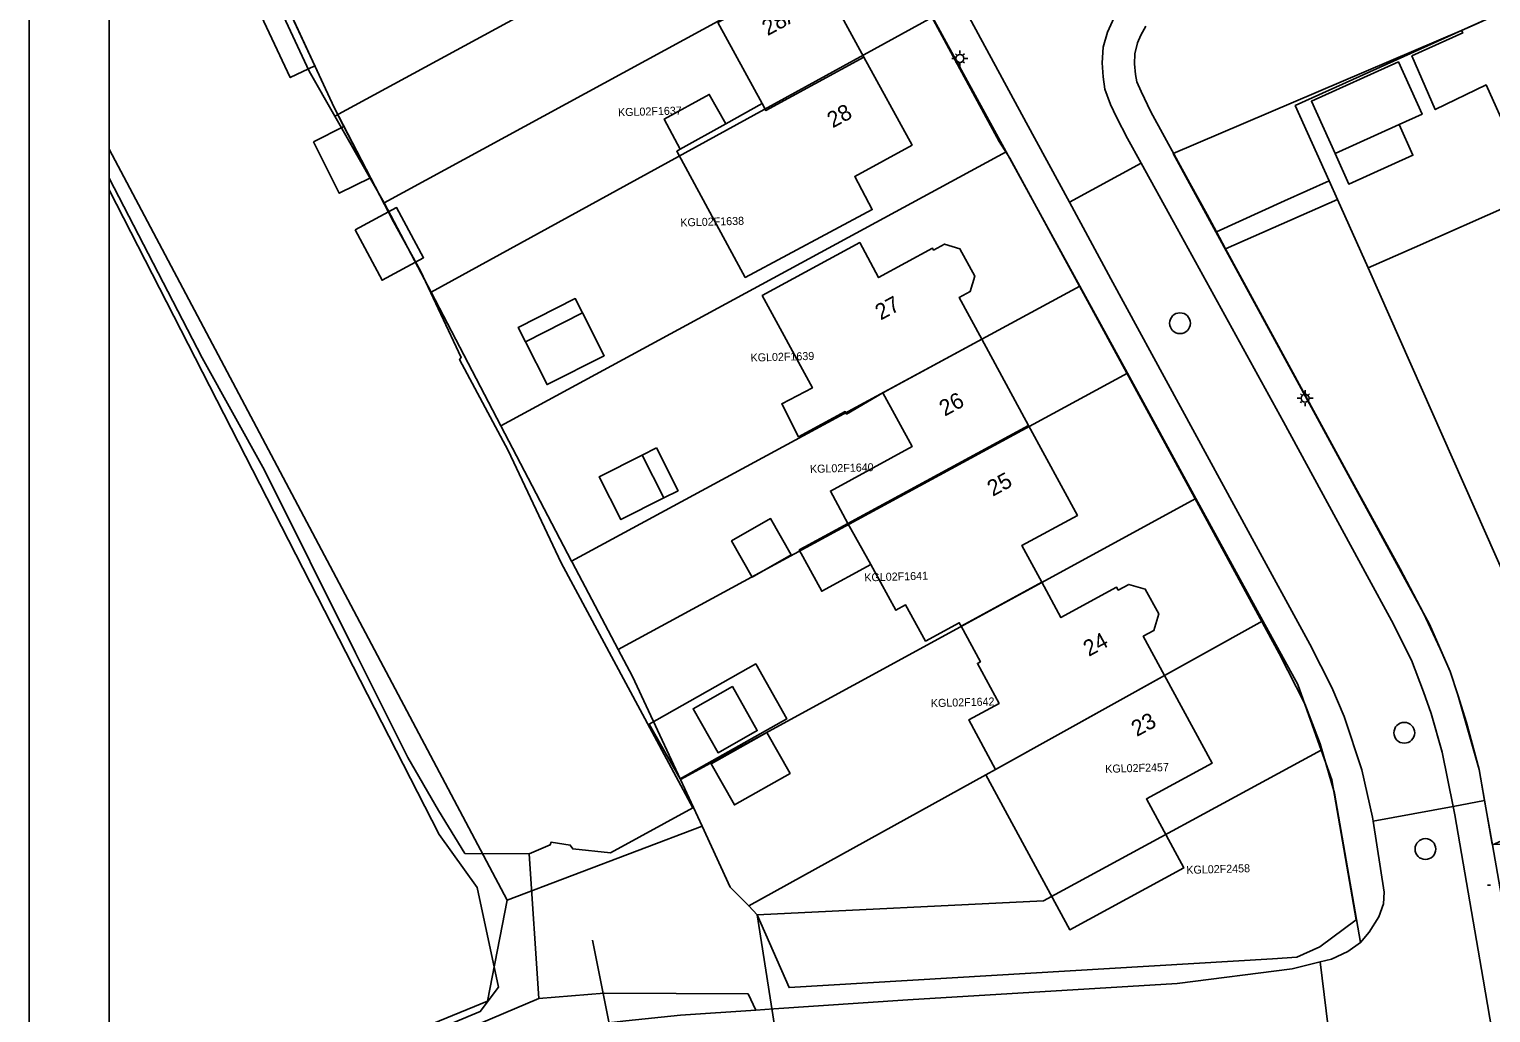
# Model space of a CAD drawing. Extents: x 124901 to 125496, y 515369 to 515789.
# Drawn here: x 124901.4 to 124992.7, y 515689 to 515750.4 of the extents above; entities that cross this region are included whole.
import ezdxf

# ---------------------------------------------------------------- set-up
doc = ezdxf.new("R2010")
doc.units = 0
for name, color, linetype in [('Alg Kaders', 7, 'Continuous'), ('Berm', 7, 'Continuous'), ('Gebouw', 7, 'Continuous'), ('Inrit', 7, 'Continuous'), ('Kunstwerkdeel', 7, 'Continuous'), ('Lichtmast', 7, 'Continuous'), ('Luifel', 7, 'Continuous'), ('Onbegroeid terrein', 7, 'Continuous'), ('Perceelnummers', 7, 'Continuous'), ('Perceelsgrenzen', 7, 'Continuous'), ('Putten', 7, 'Continuous'), ('Scheiding', 7, 'Continuous'), ('Teksten', 7, 'Continuous'), ('Vegetatie', 7, 'Continuous'), ('Voetpad', 7, 'Continuous'), ('Water', 7, 'Continuous'), ('Wegen drempel verkeerseiland', 7, 'Continuous'), ('Wegen lokale weg', 7, 'Continuous')]:
    doc.layers.add(name, color=color, linetype=linetype)

msp = doc.modelspace()

# ---------------------------------------------------------------- linework, layer by layer
at = {"layer": 'Alg Kaders'}
for points in [[(125495.925, 515789.043), (124901.425, 515789.043), (124901.425, 515368.543), (125495.925, 515368.543)], [(125490.925, 515784.043), (124906.425, 515784.043), (124906.425, 515373.543), (125490.925, 515373.543)]]:
    msp.add_lwpolyline(points, close=True, dxfattribs=at)
at = {"layer": 'Berm'}
msp.add_lwpolyline([(124906.425, 515676.84), (124909.922, 515678.313), (124922.189, 515683.579), (124929.513, 515686.462), (124932.716, 515687.441), (124934.546, 515687.912), (124936.358, 515688.167), (124938.691, 515688.452), (124942.107, 515688.795), (124946.804, 515689.111), (124946.326, 515690.139), (124937.343, 515690.17), (124933.259, 515689.839), (124919.326, 515683.927), (124906.425, 515678.456)], dxfattribs=at)
at = {"layer": 'Gebouw'}
for points in [[(124992.435, 515746.875), (124993.918, 515743.588), (125010.345, 515750.999), (125010.741, 515751.178), (125007.723, 515757.866), (124991.566, 515750.577), (124990.9, 515750.276), (124990.969, 515750.123), (124987.796, 515748.689), (124989.253, 515745.345)], [(124947.447, 515745.277), (124953.563, 515748.622), (124950.554, 515754.123), (124944.438, 515750.778), (124947.203, 515745.723)], [(124942.096, 515742.859), (124941.873, 515742.734), (124946.148, 515734.859), (124954.086, 515739.095), (124952.991, 515741.163), (124956.571, 515743.121), (124953.563, 515748.622), (124947.447, 515745.277), (124947.203, 515745.723), (124944.936, 515744.452)], [(124986.958, 515748.311), (124981.521, 515745.858), (124982.994, 515742.593), (124987, 515744.4), (124988.431, 515745.046)], [(124942.096, 515742.859), (124944.936, 515744.452), (124943.909, 515746.286), (124941.089, 515744.748)], [(124959.505, 515733.599), (124960.208, 515733.981), (124960.492, 515734.939), (124959.562, 515736.653), (124958.604, 515736.938), (124957.918, 515736.566), (124957.856, 515736.68), (124954.486, 515734.851), (124953.303, 515737.031), (124947.219, 515733.73), (124950.344, 515727.971), (124948.436, 515726.972), (124949.486, 515724.917), (124952.401, 515726.485), (124952.486, 515726.329), (124954.75, 515727.657), (124960.921, 515730.996)], [(124933.774, 515728.166), (124937.344, 515729.971), (124935.99, 515732.648), (124932.42, 515730.843)], [(124956.572, 515724.3), (124951.475, 515721.52), (124952.571, 515719.507), (124963.847, 515725.622), (124960.921, 515730.996), (124954.75, 515727.657)], [(124955.563, 515714.079), (124956.172, 515714.413), (124957.421, 515712.156), (124959.523, 515713.304), (124959.645, 515713.08), (124964.682, 515715.825), (124963.434, 515718.125), (124966.902, 515720.006), (124963.847, 515725.622), (124952.571, 515719.507), (124953.99, 515716.934), (124954.112, 515716.712)], [(124937.034, 515722.416), (124938.388, 515719.739), (124941.065, 515721.093), (124939.711, 515723.77)], [(124946.582, 515716.153), (124949.023, 515717.539), (124947.739, 515719.8), (124945.298, 515718.414)], [(124960.111, 515707.23), (124961.794, 515704.129), (124972.341, 515710.006), (124971.011, 515712.458), (124971.67, 515712.815), (124971.978, 515713.851), (124971.143, 515715.389), (124970.108, 515715.696), (124969.448, 515715.338), (124969.353, 515715.514), (124965.875, 515713.627), (124964.682, 515715.825), (124959.645, 515713.08), (124960.845, 515710.866), (124960.653, 515710.762), (124962.01, 515708.261)], [(124966.425, 515694.132), (124973.543, 515697.994), (124971.209, 515702.296), (124975.315, 515704.525), (124972.341, 515710.006), (124961.794, 515704.129), (124961.182, 515703.797)], [(124945.35, 515709.316), (124942.899, 515707.932), (124944.453, 515705.181), (124946.904, 515706.564)], [(124944.029, 515704.492), (124945.474, 515701.93), (124948.95, 515703.891), (124947.504, 515706.453)]]:
    msp.add_lwpolyline(points, close=True, dxfattribs=at)
at = {"layer": 'Inrit'}
msp.add_lwpolyline([(124975.594, 515737.699), (124976.149, 515736.646), (124983.139, 515739.734), (124982.62, 515740.889), (124979.845, 515739.652)], close=True, dxfattribs=at)
at = {"layer": 'Kunstwerkdeel'}
for points in [[(124915.267, 515752.592), (124917.728, 515747.339), (124919.268, 515748.061), (124916.832, 515753.326)], [(124919.183, 515743.334), (124920.793, 515740.112), (124922.747, 515741.089), (124921.084, 515744.284)], [(124921.775, 515737.827), (124923.468, 515734.688), (124926.062, 515736.087), (124924.37, 515739.225)]]:
    msp.add_lwpolyline(points, close=True, dxfattribs=at)
msp.add_lwpolyline([(124939.341, 515679.835), (124936.612, 515693.481)], dxfattribs=at)
at = {"layer": 'Lichtmast'}
for p, q in [((124959.349, 515748.75), (124959.279, 515748.821)), ((124959.561, 515748.838), (124959.561, 515749.038)), ((124959.773, 515748.75), (124959.844, 515748.822)), ((124959.261, 515748.539), (124959.061, 515748.538)), ((124959.349, 515748.326), (124959.277, 515748.255)), ((124959.561, 515748.238), (124959.561, 515748.038)), ((124959.773, 515748.326), (124959.843, 515748.255)), ((124959.861, 515748.538), (124960.061, 515748.538)), ((124981.122, 515727.618), (124981.122, 515727.818)), ((124980.822, 515727.319), (124980.622, 515727.318)), ((124980.91, 515727.106), (124980.838, 515727.035)), ((124980.91, 515727.53), (124980.84, 515727.601)), ((124981.122, 515727.018), (124981.122, 515726.818)), ((124981.334, 515727.53), (124981.405, 515727.602)), ((124981.334, 515727.106), (124981.404, 515727.035)), ((124981.422, 515727.318), (124981.622, 515727.318)), ((124992.715, 515696.92), (124992.515, 515696.919))]:
    msp.add_line(p, q, dxfattribs=at)
for centre in [(124959.561, 515748.538), (124981.122, 515727.318)]:
    msp.add_circle(centre, 0.25, dxfattribs=at)
at = {"layer": 'Luifel'}
for points in [[(124982.994, 515742.593), (124983.856, 515740.684), (124987.861, 515742.491), (124987, 515744.4)], [(124935.99, 515732.648), (124935.538, 515733.541), (124931.969, 515731.735), (124932.42, 515730.843)], [(124940.604, 515724.221), (124939.711, 515723.77), (124941.065, 515721.093), (124941.958, 515721.544)], [(124949.868, 515718.037), (124949.523, 515717.849), (124950.927, 515715.268), (124953.99, 515716.934), (124952.571, 515719.507)], [(124940.158, 515706.976), (124942.096, 515703.545), (124948.747, 515707.298), (124946.81, 515710.731)], [(124944.453, 515705.181), (124942.899, 515707.932), (124945.35, 515709.316), (124946.904, 515706.564)]]:
    msp.add_lwpolyline(points, close=True, dxfattribs=at)
at = {"layer": 'Onbegroeid terrein'}
for points in [[(124916.618, 515753.787), (124920.468, 515745.467), (124924.184, 515738.328), (124925.873, 515735.275), (124928.397, 515729.851), (124928.311, 515729.738), (124931.351, 515724.06), (124934.651, 515717.039), (124942.88, 515701.747), (124937.733, 515698.928), (124935.373, 515699.178), (124935.223, 515699.423), (124934.039, 515699.601), (124933.973, 515699.441), (124932.658, 515698.862), (124933.259, 515689.839), (124937.343, 515690.17), (124946.326, 515690.139), (124946.804, 515689.111), (124947.93, 515689.187), (124956.314, 515689.751), (124973.14, 515690.777), (124980.32, 515691.695), (124982.059, 515692.12), (124982.77, 515692.294), (124983.796, 515692.765), (124984.587, 515693.335), (124984.256, 515695.245), (124982.971, 515702.653), (124982.067, 515705.75), (124981.112, 515708.231), (124979.504, 515711.383), (124972.903, 515723.54), (124962.689, 515742.297), (124962.015, 515743.343), (124941.47, 515781.335)], [(124950.554, 515754.123), (124953.563, 515748.622), (124956.571, 515743.121), (124952.991, 515741.163), (124954.086, 515739.095), (124946.148, 515734.859), (124941.873, 515742.734), (124942.096, 515742.859), (124941.089, 515744.748), (124943.909, 515746.286), (124944.936, 515744.452), (124947.203, 515745.723), (124944.438, 515750.778)], [(124993.918, 515743.588), (124992.435, 515746.875), (124989.253, 515745.345), (124987.796, 515748.689), (124990.969, 515750.123), (124990.9, 515750.276), (124980.509, 515745.589), (124982.62, 515740.889), (124983.139, 515739.734), (124985.058, 515735.461), (124987.951, 515736.739), (125000, 515742.06)]]:
    msp.add_lwpolyline(points, dxfattribs=at)
for points in [[(125021.18, 515738.216), (125016.204, 515749.216), (125014.573, 515748.496), (125000, 515742.06), (124987.951, 515736.739), (124985.058, 515735.461), (124999.673, 515702.472), (125000, 515702.617), (125030.815, 515716.274), (125023.591, 515732.888)], [(124981.521, 515745.858), (124986.958, 515748.311), (124988.431, 515745.046), (124987, 515744.4), (124982.994, 515742.593)], [(124961.794, 515704.129), (124960.111, 515707.23), (124962.01, 515708.261), (124960.653, 515710.762), (124960.845, 515710.866), (124959.645, 515713.08), (124959.523, 515713.304), (124957.421, 515712.156), (124956.172, 515714.413), (124955.563, 515714.079), (124954.112, 515716.712), (124953.99, 515716.934), (124952.571, 515719.507), (124951.475, 515721.52), (124956.572, 515724.3), (124954.75, 515727.657), (124952.486, 515726.329), (124952.401, 515726.485), (124949.486, 515724.917), (124948.436, 515726.972), (124950.344, 515727.971), (124947.219, 515733.73), (124953.303, 515737.031), (124954.486, 515734.851), (124957.856, 515736.68), (124957.918, 515736.566), (124958.604, 515736.938), (124959.562, 515736.653), (124960.492, 515734.939), (124960.208, 515733.981), (124959.505, 515733.599), (124960.921, 515730.996), (124963.847, 515725.622), (124966.902, 515720.006), (124963.434, 515718.125), (124964.682, 515715.825), (124965.875, 515713.627), (124969.353, 515715.514), (124969.448, 515715.338), (124970.108, 515715.696), (124971.143, 515715.389), (124971.978, 515713.851), (124971.67, 515712.815), (124971.011, 515712.458), (124972.341, 515710.006), (124975.315, 515704.525), (124971.209, 515702.296), (124973.543, 515697.994), (124966.425, 515694.132), (124961.182, 515703.797)], [(124937.344, 515729.971), (124933.774, 515728.166), (124932.42, 515730.843), (124935.99, 515732.648)], [(124938.388, 515719.739), (124937.034, 515722.416), (124939.711, 515723.77), (124941.065, 515721.093)], [(124949.023, 515717.539), (124946.582, 515716.153), (124945.298, 515718.414), (124947.739, 515719.8)], [(124942.899, 515707.932), (124945.35, 515709.316), (124946.904, 515706.564), (124944.453, 515705.181)], [(124944.029, 515704.492), (124947.504, 515706.453), (124948.95, 515703.891), (124945.474, 515701.93)]]:
    msp.add_lwpolyline(points, close=True, dxfattribs=at)
at = {"layer": 'Perceelsgrenzen'}
for points in [[(124939.831, 515784.043), (124942.181, 515779.749), (124947.7, 515769.665), (124951.905, 515761.983), (124954.881, 515756.546), (124957.852, 515751.118), (124962.459, 515742.701), (124967.05, 515734.312), (124970.025, 515728.876), (124974.299, 515721.067), (124978.481, 515713.427), (124980.664, 515709.438), (124982.132, 515705.346), (124982.796, 515703.495), (124984.315, 515694.743), (124982.043, 515693.067), (124980.61, 515692.413), (124979.086, 515692.308), (124948.888, 515690.522), (124946.892, 515695.063), (124949.333, 515679.527)], [(124906.425, 515773.675), (124907.898, 515770.764), (124911.623, 515763.401), (124916.573, 515752.754), (124918.909, 515747.729), (124920.514, 515744.921), (124923.602, 515739.522), (124926.526, 515733.933), (124930.887, 515725.594), (124935.308, 515717.138), (124935.342, 515717.073), (124938.219, 515711.628), (124939.11, 515709.943), (124942.106, 515703.52), (124943.454, 515700.593), (124931.273, 515695.979), (124906.425, 515742.864)], [(124906.425, 515742.864), (124931.273, 515695.979), (124930.052, 515689.675), (124906.425, 515679.992)], [(124906.425, 515679.992), (124930.052, 515689.675), (124931.273, 515695.979), (124943.454, 515700.593), (124945.202, 515696.797), (124946.369, 515695.624), (124946.892, 515695.063), (124949.333, 515679.527), (124950.559, 515671.725), (124944.847, 515671.033), (124938.462, 515670.08), (124938.039, 515676.742), (124932.267, 515677.429), (124931.302, 515679.813), (124927.728, 515678.841), (124906.425, 515670.235)]]:
    msp.add_lwpolyline(points, dxfattribs=at)
for points in [[(124988.906, 515713.205), (124972.893, 515742.592), (124990.9, 515750.276), (125007.671, 515757.842), (125002.477, 515769.567), (125026.186, 515779.978), (125040.828, 515746.88), (125037.558, 515745.497), (125057.095, 515701.642), (125041.951, 515699.428), (124992.815, 515699.484), (124991.996, 515704.137), (124990.673, 515708.803), (124990.18, 515710.264)], [(124947.7, 515769.665), (124951.905, 515761.983), (124920.514, 515744.921), (124918.909, 515747.729), (124916.573, 515752.754)], [(124951.905, 515761.983), (124954.881, 515756.546), (124923.602, 515739.522), (124920.514, 515744.921)], [(124972.893, 515742.592), (124988.906, 515713.205), (124990.18, 515710.264), (124990.673, 515708.803), (124991.996, 515704.137), (124992.815, 515699.484), (125041.951, 515699.428), (125057.095, 515701.642), (125037.558, 515745.497), (125037.493, 515745.642), (125024.246, 515739.7), (125017.617, 515754.699), (125013.263, 515760.497), (125007.723, 515757.866), (125007.671, 515757.842), (124990.9, 515750.276)], [(124954.881, 515756.546), (124957.852, 515751.118), (124926.526, 515733.933), (124923.602, 515739.522)], [(124926.526, 515733.933), (124957.852, 515751.118), (124962.459, 515742.701), (124930.887, 515725.594)], [(124930.887, 515725.594), (124962.459, 515742.701), (124967.05, 515734.312), (124935.308, 515717.138)], [(124935.308, 515717.138), (124967.05, 515734.312), (124970.025, 515728.876), (124938.219, 515711.628), (124935.342, 515717.073)], [(124938.219, 515711.628), (124970.025, 515728.876), (124974.299, 515721.067), (124942.106, 515703.52), (124939.11, 515709.943)], [(124942.106, 515703.52), (124974.299, 515721.067), (124978.481, 515713.427), (124961.794, 515704.129), (124961.182, 515703.797), (124946.369, 515695.624), (124945.202, 515696.797), (124943.454, 515700.593)], [(124946.369, 515695.624), (124961.182, 515703.797), (124961.794, 515704.129), (124978.481, 515713.427), (124980.664, 515709.438), (124982.132, 515705.346), (124964.791, 515695.928), (124946.892, 515695.063)], [(124946.892, 515695.063), (124964.791, 515695.928), (124982.132, 515705.346), (124982.796, 515703.495), (124984.315, 515694.743), (124982.043, 515693.067), (124980.61, 515692.413), (124979.086, 515692.308), (124948.888, 515690.522)]]:
    msp.add_lwpolyline(points, close=True, dxfattribs=at)
at = {"layer": 'Putten'}
for centre in [(124973.31, 515732), (124987.32, 515706.43), (124988.64, 515699.17)]:
    msp.add_circle(centre, 0.65, dxfattribs=at)
at = {"layer": 'Scheiding'}
for points in [[(124990.9, 515750.276), (124980.509, 515745.589)], [(124921.084, 515744.284), (124920.468, 515745.467), (124919.268, 515748.061)], [(124980.509, 515745.589), (124982.62, 515740.889)], [(124962.689, 515742.297), (124962.015, 515743.343)], [(124987.951, 515736.739), (125000, 515742.06)], [(124982.62, 515740.889), (124983.139, 515739.734)], [(124983.139, 515739.734), (124985.058, 515735.461)], [(124985.058, 515735.461), (124987.951, 515736.739)], [(124999.673, 515702.472), (124985.058, 515735.461)], [(124932.658, 515698.862), (124928.644, 515698.897)]]:
    msp.add_lwpolyline(points, dxfattribs=at)
at = {"layer": 'Vegetatie'}
for points in [[(124971.166, 515750.557), (124970.855, 515749.979), (124970.646, 515749.501), (124970.49, 515748.829), (124970.461, 515748.2), (124970.528, 515747.54), (124970.619, 515747.076), (124970.875, 515746.47), (124971.487, 515745.208), (124973.931, 515740.739), (124974.998, 515738.788), (124975.594, 515737.699), (124979.845, 515739.652), (124982.62, 515740.889), (124980.509, 515745.589), (124990.9, 515750.276), (124991.566, 515750.577)], [(124906.425, 515679.348), (124929.594, 515689.031), (124930.739, 515690.555), (124929.416, 515696.773), (124927.035, 515700.08), (124906.425, 515740.33)]]:
    msp.add_lwpolyline(points, dxfattribs=at)
msp.add_lwpolyline([(124983.932, 515722.346), (124987.069, 515716.675), (124988.528, 515713.905), (124989.572, 515711.678), (124990.18, 515710.264), (124990.673, 515708.803), (124991.209, 515707.068), (124991.996, 515704.137), (124992.338, 515702.198), (124992.824, 515699.435), (124999.673, 515702.472), (124985.058, 515735.461), (124983.139, 515739.734), (124976.149, 515736.646)], close=True, dxfattribs=at)
at = {"layer": 'Voetpad'}
for points in [[(124941.47, 515781.335), (124962.015, 515743.343), (124962.689, 515742.297), (124972.903, 515723.54), (124979.504, 515711.383), (124981.112, 515708.231), (124982.067, 515705.75), (124982.971, 515702.653), (124984.256, 515695.245), (124984.587, 515693.335), (124985.126, 515693.99), (124985.737, 515694.947), (124986.022, 515695.747), (124986.063, 515696.474), (124985.381, 515700.914), (124985.344, 515701.152), (124984.675, 515704.124), (124983.561, 515707.443), (124982.789, 515709.258), (124981.42, 515711.957), (124977.687, 515718.787), (124968.993, 515734.773), (124966.404, 515739.549), (124963.703, 515744.533), (124956.475, 515757.887)], [(124969.402, 515751.548), (124968.772, 515750.169), (124968.515, 515749.247), (124968.447, 515748.251), (124968.503, 515747.378), (124968.615, 515746.614), (124968.971, 515745.659), (124969.339, 515744.865), (124970.037, 515743.532), (124970.886, 515741.988), (124972.895, 515738.335), (124979.782, 515725.852), (124985.008, 515716.224), (124986.522, 515713.435), (124987.774, 515710.974), (124988.52, 515708.992), (124988.995, 515707.643), (124989.679, 515705.228), (124990.364, 515701.833), (124992.338, 515702.198), (124991.996, 515704.137), (124991.209, 515707.068), (124990.673, 515708.803), (124990.18, 515710.264), (124989.572, 515711.678), (124988.528, 515713.905), (124987.069, 515716.675), (124983.932, 515722.346), (124976.149, 515736.646), (124975.594, 515737.699), (124974.998, 515738.788), (124973.931, 515740.739), (124971.487, 515745.208), (124970.875, 515746.47), (124970.619, 515747.076), (124970.528, 515747.54), (124970.461, 515748.2), (124970.49, 515748.829), (124970.646, 515749.501), (124970.855, 515749.979), (124971.166, 515750.557)], [(124996.102, 515676.41), (124993.7, 515690.631), (124993.363, 515692.627), (124993.708, 515694.415), (124992.824, 515699.435), (124992.338, 515702.198), (124990.364, 515701.833), (124990.47, 515701.306), (124992.256, 515691.049), (124993.89, 515681.429)]]:
    msp.add_lwpolyline(points, dxfattribs=at)
at = {"layer": 'Water'}
for points in [[(124906.425, 515741.068), (124912.236, 515729.85), (124916.128, 515722.818), (124921.808, 515711.428), (124925.068, 515704.877), (124926.991, 515701.572), (124928.644, 515698.897), (124932.658, 515698.862), (124933.973, 515699.441), (124934.039, 515699.601), (124935.223, 515699.423), (124935.373, 515699.178), (124937.733, 515698.928), (124942.88, 515701.747), (124934.651, 515717.039), (124931.351, 515724.06), (124928.311, 515729.738), (124928.397, 515729.851), (124925.873, 515735.275), (124924.184, 515738.328), (124920.468, 515745.467), (124916.618, 515753.787)], [(124906.425, 515678.456), (124919.326, 515683.927), (124933.259, 515689.839), (124932.658, 515698.862), (124928.644, 515698.897), (124926.991, 515701.572), (124925.068, 515704.877), (124921.808, 515711.428), (124916.128, 515722.818), (124912.236, 515729.85), (124906.425, 515741.068)], [(124906.425, 515740.33), (124927.035, 515700.08), (124929.416, 515696.773), (124930.739, 515690.555), (124929.594, 515689.031), (124906.425, 515679.348)]]:
    msp.add_lwpolyline(points, dxfattribs=at)
at = {"layer": 'Wegen drempel verkeerseiland'}
for points in [[(124956.475, 515757.887), (124963.703, 515744.533), (124966.404, 515739.549), (124970.886, 515741.988), (124970.037, 515743.532), (124969.339, 515744.865), (124968.971, 515745.659), (124968.615, 515746.614), (124968.503, 515747.378), (124968.447, 515748.251), (124968.515, 515749.247), (124968.772, 515750.169), (124969.402, 515751.548)], [(124993.89, 515681.429), (124992.256, 515691.049), (124990.47, 515701.306), (124990.364, 515701.833), (124985.381, 515700.914), (124986.063, 515696.474), (124986.022, 515695.747), (124985.737, 515694.947), (124985.126, 515693.99), (124984.587, 515693.335), (124983.796, 515692.765), (124982.77, 515692.294), (124982.059, 515692.12), (124982.684, 515687.033)]]:
    msp.add_lwpolyline(points, dxfattribs=at)
at = {"layer": 'Wegen lokale weg'}
msp.add_lwpolyline([(124989.679, 515705.228), (124988.995, 515707.643), (124988.52, 515708.992), (124987.774, 515710.974), (124986.522, 515713.435), (124985.008, 515716.224), (124979.782, 515725.852), (124972.895, 515738.335), (124970.886, 515741.988), (124966.404, 515739.549), (124968.993, 515734.773), (124977.687, 515718.787), (124981.42, 515711.957), (124982.789, 515709.258), (124983.561, 515707.443), (124984.675, 515704.124), (124985.344, 515701.152), (124985.381, 515700.914), (124990.364, 515701.833)], close=True, dxfattribs=at)
msp.add_lwpolyline([(124982.684, 515687.033), (124982.059, 515692.12), (124980.32, 515691.695), (124973.14, 515690.777), (124956.314, 515689.751), (124947.93, 515689.187), (124946.804, 515689.111), (124942.107, 515688.795)], dxfattribs=at)

# ---------------------------------------------------------------- texts
at = {"layer": 'Perceelnummers'}
for s, rotation, p in [('KGL02F1637', 1.62914, (124938.213, 515744.921)), ('KGL02F1638', 1.62918, (124942.106, 515738.037)), ('KGL02F1639', 1.62923, (124946.492, 515729.601)), ('KGL02F1640', 1.62928, (124950.202, 515722.651)), ('KGL02F1641', 1.62932, (124953.598, 515715.879)), ('KGL02F1642', 1.62936, (124957.752, 515708.027)), ('KGL02F2457', 1.62949, (124968.645, 515703.926)), ('KGL02F2458', 1.62955, (124973.714, 515697.615))]:
    msp.add_text(s, height=0.5, rotation=rotation, dxfattribs=at).set_placement(p)
at = {"layer": 'Teksten'}
for s, rotation, p in [('28A', 28.7, (124947.551, 515749.921)), ('28', 28.7, (124951.615, 515744.161)), ('27', 28.5, (124954.612, 515732.163)), ('26', 28.6, (124958.614, 515726.162)), ('25', 28.6, (124961.614, 515721.162)), ('24', 28.5, (124967.612, 515711.163)), ('23', 28.5, (124970.612, 515706.163))]:
    msp.add_text(s, height=1, rotation=rotation, dxfattribs=at).set_placement(p)

doc.saveas('drawing.dxf')
